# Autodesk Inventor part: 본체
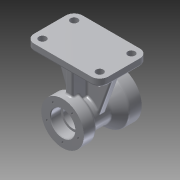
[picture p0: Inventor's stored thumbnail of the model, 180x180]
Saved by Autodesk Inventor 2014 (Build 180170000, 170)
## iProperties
Created: 2015-08
Part Number: 본체
Material: 알루미늄 6061
Document SubType Name: Modeling
Designer: SEC
Density: 2.71 g/cm^3
Appearance: 알루미늄 - 평지
Mass: 1061.77 g
Surface Area: 752.134 cm^2
Volume: 391.795 cm^3
Author: SEC
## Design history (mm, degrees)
sketch "스케치1"
  geometry: L1 (0, 0)-(90, 0); L2 (90, 0)-(90, 40); L3 (90, 40)-(70, 40); L4 (25.196, 26)-(20, 35); L5 (0, 0)-(0, 35); L6 (0, 35)-(20, 35); L7 (70, 40)-(53.315, 26); L8 (53.315, 26)-(25.196, 26)
  constraints: 16 end point, 2 parallel, 2 perpendicular, 1 horizontal
  dimensions: "d0" = 90 distance of L1.start L1.end; "d2" = 20 distance of L5.end L4.end; "d3" = 70 diameter of L6 L1; "d4" = 80 diameter of L3 L1; "d5" = 20 distance of L2.end L3.end; "d7" = 40 deg angle of L8 L7; "d8" = 60 deg angle of L8 L4; "d9" = 52 diameter of L8 L1
revolve "회전1" sketch "스케치1" stored, may be unused: angle "d10" = 90 deg
sketch "스케치2"
  geometry: C1 r 35 at (0, 0) reference; C2 r 20 at (0, 0)
  constraints: 1 centre point, 1 coincident
  dimensions: "d11" = 40 diameter of C2
extrude "돌출1" cut sketch "스케치2" distance "d12" = 17; taper "d13" = 0 deg
sketch "스케치3"
  geometry: C1 r 20 at (0, 0) reference; C2 r 16 at (0, 0)
  constraints: 1 centre point, 1 coincident
  dimensions: "d14" = 32 diameter of C2
extrude "돌출2" cut sketch "스케치3" stored distance "d15" = 17; taper "d16" = 0 deg
sketch "스케치4"
  geometry: C1 r 16 at (0, 0) reference; C2 r 40 at (0, 0) reference; C3 r 26 at (0, 0)
  constraints: 1 centre point, 1 coincident
  dimensions: "d17" = 52 diameter of C3
extrude "돌출3" cut sketch "스케치4" distance "d18" = 20; taper "d19" = 0 deg
sketch "스케치5"
  geometry: C1 r 16 at (0, 0) reference; C2 r 26 at (0, 0) reference; C3 r 19 at (0, 0)
  constraints: 1 centre point, 1 coincident
  dimensions: "d20" = 38 diameter of C3
extrude "돌출4" cut sketch "스케치5" distance "d21" = 3; taper "d22" = 0 deg
chamfer "모따기1" distance "d23" = 1; stored, may be unused: second distance "d24" = 2, angle "d25" = 45 deg
fillet "모깎기1" dims "d26" = 0.3
sketch "스케치6" dims "d27" = 54
  geometry: C1 r 21 at (0, 0) reference; 2 further points
  constraints: 1 coincident, 1 vertical alignment, 2 other
hole "구멍1" sketch "스케치6" at (0, -27) diameter "d28" = 3.459; stored, may be unused: countersink angle "d32" = 82 deg, drill point angle "d34" = 118 deg; dims "d29" = 10, "d30" = 3.023, "d31" = 20, "d33" = 13
sketch "스케치7"
  geometry: 1 further point
hole "구멍2" sketch "스케치7" at (0, 33) diameter "d39" = 3.459; stored, may be unused: countersink angle "d43" = 82 deg, drill point angle "d45" = 118 deg; dims "d40" = 10, "d41" = 3.023, "d42" = 20, "d44" = 13
sketch "스케치8"
  geometry: L1 (61, 78)-(-61, 78); L2 (-61, 78)-(-61, 90); L3 (-61, 90)-(61, 90); L4 (61, 90)-(61, 78); C1 r 35 at (0, 0) reference; 1 further point
  constraints: 8 end point, 2 parallel, 1 horizontal, 1 midpoint, 1 perpendicular, 1 vertical alignment
  dimensions: "d49" = 12 distance between parallel lines of L3 L1; "d50" = 122 distance of L2.end L3.end; "d51" = 90 distance from line of L3 C1.centre
extrude "돌출5" join sketch "스케치8" distance "d52" = 80; taper "d53" = 0 deg
fillet "모깎기2" dims "d54" = 14
sketch "스케치9"
  geometry: L1 (70, 25.7)-(70, 19) reference; L2 (70, 19)-(67, 19) reference; L3 (67, 19)-(67, 16) reference; L4 (67, 16)-(17, 16) reference; L5 (17, 16)-(17, 19.7) reference; L6 (16.7, 20)-(1, 20) reference; L7 (1, 20)-(0, 21) reference; L8 (0, 21)-(0, 35) reference; L9 (0, 35)-(20, 35) reference; L10 (20, 35)-(25.196, 26) reference; L11 (25.196, 26)-(53.315, 26) reference; L12 (53.315, 26)-(70, 40) reference; L13 (70, 40)-(90, 40) reference; L14 (90, 40)-(90, 27) reference; L15 (90, 27)-(89, 26) reference; L16 (89, 26)-(70.3, 26) reference; L17 (70.3, -26)-(89, -26) reference; L18 (89, -26)-(90, -27) reference; L19 (90, -27)-(90, -31.271) reference; L20 (90, -31.271)-(77, -31.271) reference; L21 (77, -31.271)-(75.961, -33) reference; L22 (75.961, -33)-(77, -34.73) reference; L23 (77, -34.73)-(90, -34.73) reference; L24 (90, -34.73)-(90, -40) reference; L25 (90, -40)-(70, -40) reference; L26 (70, -40)-(53.315, -26) reference; L27 (53.315, -26)-(25.196, -26) reference; L28 (25.196, -26)-(20, -35) reference; L29 (20, -35)-(0, -35) reference; L30 (0, -35)-(0, -28.73) reference; L31 (0, -28.73)-(13, -28.73) reference; L32 (13, -28.73)-(14.039, -27) reference; L33 (14.039, -27)-(13, -25.27) reference; L34 (13, -25.27)-(0, -25.27) reference; L35 (0, -25.27)-(0, -21) reference; L36 (0, -21)-(1, -20) reference; L37 (1, -20)-(16.7, -20) reference; L38 (17, -19.7)-(17, -16) reference; L39 (17, -16)-(67, -16) reference; L40 (67, -16)-(67, -19) reference; L41 (67, -19)-(70, -19) reference; L42 (70, -19)-(70, -25.7) reference; L43 (0, 90)-(80, 90) reference; L44 (80, 90)-(80, 78) reference; L45 (80, 78)-(0, 78) reference; L46 (0, 78)-(0, 90) reference; L47 (10, 78)-(10, 22.702); L48 (10, 22.702)-(66.512, 22.702); L49 (66.512, 22.702)-(77.452, 35.74); L50 (77.452, 35.74)-(70, 78); L51 (10, 81.423)-(10, 78); L52 (70, 78)-(70, 81.423); L53 (70, 81.423)-(10, 81.423); A1 r 0.3 centre (70.3, 25.7) between (70.3, 26) and (70, 25.7) reference; A2 r 0.3 centre (16.7, 19.7) between (17, 19.7) and (16.7, 20) reference; A3 r 0.3 centre (70.3, -25.7) between (70, -25.7) and (70.3, -26) reference; A4 r 0.3 centre (16.7, -19.7) between (16.7, -20) and (17, -19.7) reference; 1 further point
  constraints: 14 end point, 4 perpendicular, 2 parallel, 2 point on line
  dimensions: "d56" = 10 distance between parallel lines of L47 L46; "d57" = 10 distance from line of L50.end L44; "d58" = 80 deg angle of L45 L50; "d59" = 112.69366 distance between parallel lines of L20 L53; "d60" = 53.97268 distance between parallel lines of L20 L48; "d61" = 6.87424 distance from line of L13.end L49
extrude "돌출6" join sketch "스케치9" stored distance "d62" = 12; taper "d63" = 0 deg
node "작업 평면1"
sketch "스케치10"
  geometry: L1 (-61, 78)-(-61, 90) reference; L2 (-61, 90)-(61, 90) reference; L3 (61, 90)-(61, 78) reference; L4 (61, 78)-(6, 78) reference; L5 (6, 78)-(6, 25.298) reference; L6 (-6, 25.298)-(-6, 78) reference; L7 (-6, 78)-(-61, 78) reference; L8 (-61, 78)-(-61, 90) reference; L9 (-61, 90)-(61, 90) reference; L10 (61, 90)-(61, 78) reference; L11 (61, 78)-(6, 78) reference; L12 (6, 78)-(6, 25.298) reference; L13 (-6, 25.298)-(-6, 78) reference; L14 (-6, 78)-(-61, 78) reference; L15 (-51, 78)-(-25.091, 6.815); L16 (-25.091, 6.815)-(-17.423, 12.488); L17 (-17.423, 12.488)-(0, 22.447); L18 (51, 78)-(25.091, 6.815); L19 (25.091, 6.815)-(0, 22.447); L20 (51, 78)-(51, 82.847); L21 (51, 82.847)-(-51, 82.847); L22 (-51, 82.847)-(-51, 78); C1 r 16 at (0, 0) reference; C2 r 16 at (0, 0) reference; A1 r 26 centre (0, 0) between (-6, 25.298) and (6, 25.298) reference; A2 r 26 centre (0, 0) between (-6, 25.298) and (6, 25.298) reference; 1 further point
  constraints: 16 end point, 2 perpendicular, 1 parallel, 1 point on circle, 1 point on line
  dimensions: "d64" = 70 deg angle of L15 L7; "d65" = 10 distance from line of L15.start L1; "d66" = 20 deg angle of L3 L18; "d67" = 58.0777 deg angle of L3 L19; "d68" = 119.751 deg angle of L3 L17; "d69" = 126.493 deg angle of L3 L16; "d70" = 10 distance between parallel lines of L3 L20; "d71" = 4.8472 distance between parallel lines of L4 L21; "d72" = 5.29268 distance from line of L2.end L18; "d73" = 89.59198 distance from line of L2.end L19; "d74" = 28.37837 distance from line of L2.end L17
extrude "돌출7" join sketch "스케치10" stored distance "d75" = 12; taper "d76" = 0 deg
sketch "스케치11"
  geometry: C1 r 6 at (0, 66); C2 r 6 at (0, 14); C3 r 6 at (94, 14); C4 r 6 at (94, 66); A1 r 14 centre (0, 14) between (-14, 14) and (0, 0) reference; A2 r 14 centre (94, 14) between (94, 0) and (108, 14) reference; A3 r 14 centre (94, 66) between (108, 66) and (94, 80) reference; A4 r 14 centre (0, 66) between (0, 80) and (-14, 66) reference; 1 further point
  constraints: 4 centre point, 4 coincident
  dimensions: "d77" = 12 diameter of C1; "d78" = 12 diameter of C2; "d79" = 12 diameter of C3; "d80" = 12 diameter of C4
extrude "돌출8" cut sketch "스케치11" distance "d81" = 15; taper "d82" = 0 deg
sketch "스케치12"
  geometry: L1 (-25.091, 6.815)-(-51, 78) reference; L2 (-51, 78)-(-61, 78) reference; L3 (-61, 78)-(-61, 90) reference; L4 (-61, 90)-(61, 90) reference; L5 (61, 90)-(61, 78) reference; L6 (61, 78)-(51, 78) reference; L7 (51, 78)-(25.091, 6.815) reference; L8 (18, 54)-(18, 60); L9 (30, 54)-(30, 60); L10 (24, 48)-(24, 48); L11 (24, 66)-(24, 66); L12 (-24, 66)-(-24, 66); L13 (-24, 48)-(-24, 48); L14 (-30, 54)-(-30, 60); L15 (-18, 54)-(-18, 60); C1 r 16 at (0, 0) reference; A1 r 26 centre (0, 0) between (-25.091, 6.815) and (25.091, 6.815) reference; A2 r 6 centre (24, 54) between (24, 48) and (30, 54); A3 r 6 centre (24, 54) between (18, 54) and (24, 48); A4 r 6 centre (24, 60) between (30, 60) and (24, 66); A5 r 6 centre (24, 60) between (24, 66) and (18, 60); A6 r 6 centre (-24, 60) between (-24, 66) and (-30, 60); A7 r 6 centre (-24, 54) between (-30, 54) and (-24, 48); A8 r 6 centre (-24, 60) between (-18, 60) and (-24, 66); A9 r 6 centre (-24, 54) between (-24, 48) and (-18, 54); 1 further point
  constraints: 16 end point, 16 point on circle, 8 centre point, 8 tangent, 2 concentric, 2 perpendicular
  dimensions: "d88" = 6 radius of A2; "d89" = 6 radius of A4; "d90" = 18 distance of L11.start L10.start; "d91" = 12 distance between parallel lines of L8 L9
extrude "돌출9" cut sketch "스케치12" stored distance "d94" = 15; taper "d95" = 0 deg
sketch "스케치13"
  geometry: L1 (34.482, 10)-(78, 10) reference; L2 (78, 34)-(78, 10) reference; 2 further points
  constraints: 1 other
  dimensions: "d96" = 16 distance from line of point (54, 26) L1; "d97" = 24 distance from line of point (54, 26) L2
feature "엠보싱1" sketch "스케치13" dims "d98" = 0.5, "d99" = 0
fillet "모깎기3" dims "d100" = 5
fillet "모깎기4" dims "d101" = 3
fillet "모깎기5" dims "d102" = 3
fillet "모깎기6" dims "d103" = 3
fillet "모깎기7" dims "d104" = 3
node "솔리드1"
pattern_circular "원형 패턴1" dims angle "d36" = 360 deg
pattern_circular "원형 패턴2" dims angle "d47" = 360 deg
node "절단 모서리 투영1"
node "절단 모서리 투영2"
node "절단 모서리 투영3"
node "절단 모서리 투영4"
